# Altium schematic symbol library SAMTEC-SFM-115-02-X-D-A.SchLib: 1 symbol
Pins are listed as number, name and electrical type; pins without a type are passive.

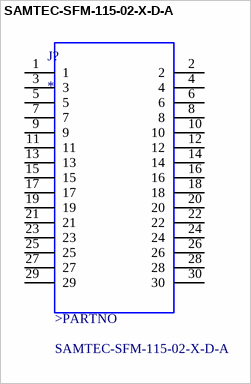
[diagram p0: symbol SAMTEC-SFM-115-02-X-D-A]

## SAMTEC-SFM-115-02-X-D-A
designator J?
MP: SAMTEC-SFM-115-02-X-D-A; MF: Samtec Inc.
footprint SAMTEC-SFM-115-02-X-D-A
pins: 1, 2, 3, 4, 5, 6, 7, 8, 9, 10, 11, 12, 13, 14, 15, 16, 17, 18, 19, 20, 21, 22, 23, 24, 25, 26, 27, 28, 29, 30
